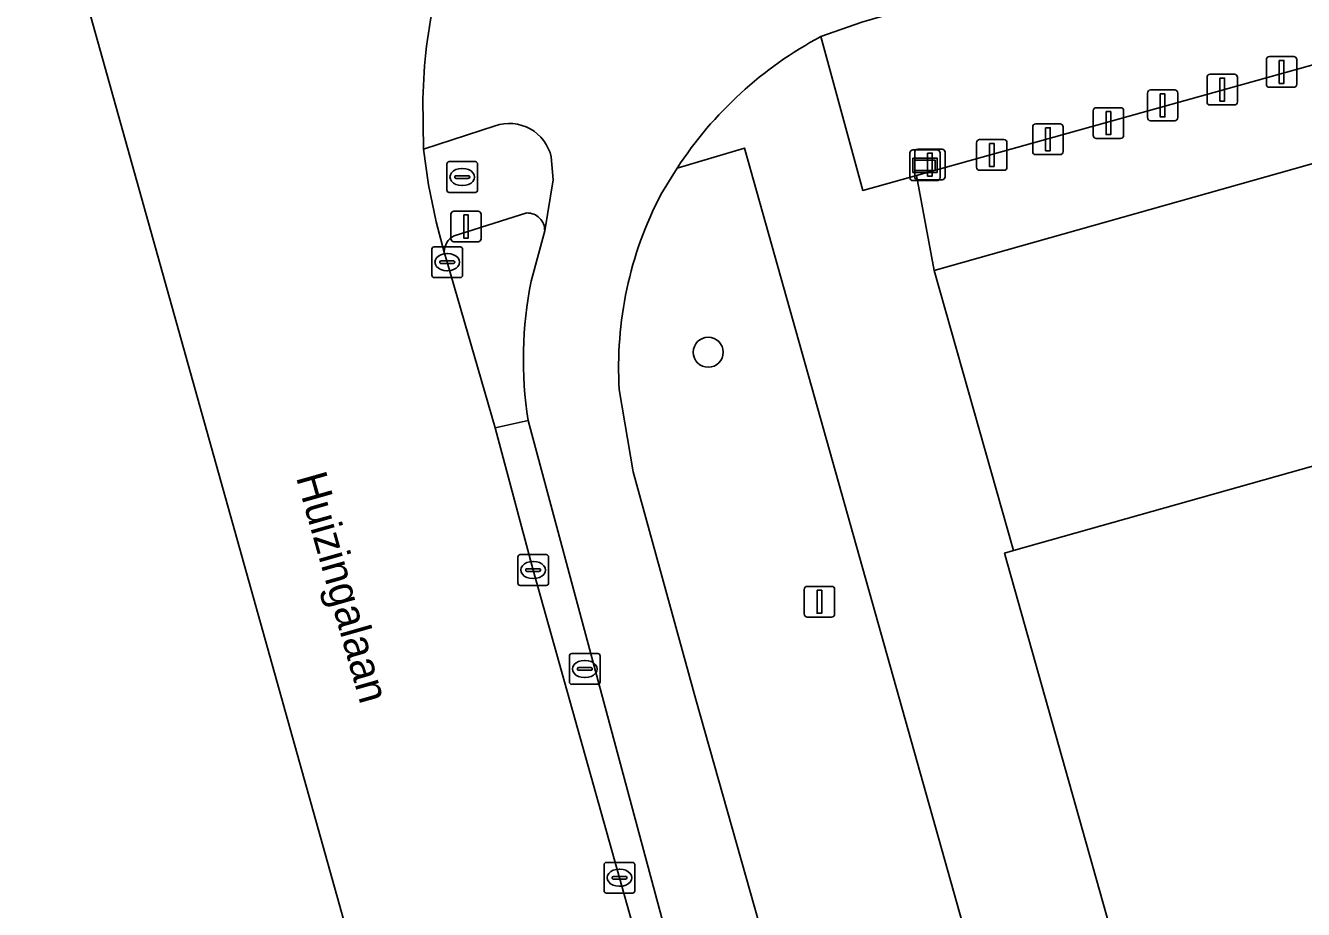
# Model space of a CAD drawing. Extents: x 159680 to 160786, y 387323 to 388340.
# Drawn here: x 159679.9 to 159721.53, y 388136.03 to 388164.81 of the extents above; entities that cross this region are included whole.
import ezdxf

# ---------------------------------------------------------------- set-up
doc = ezdxf.new("R2010")
doc.units = 0
for name, color, linetype in [('IMGEO_Afsluitpaal', 7, 'Continuous'), ('IMGEO_Berm_groen', 7, 'Continuous'), ('IMGEO_Berm_open', 7, 'Continuous'), ('IMGEO_Boom', 7, 'Continuous'), ('IMGEO_Fietspad_gesloten', 7, 'Continuous'), ('IMGEO_Groenvoorziening', 7, 'Continuous'), ('IMGEO_Kolk', 7, 'Continuous'), ('IMGEO_Lichtmast', 7, 'Continuous'), ('IMGEO_Openbare_ruimte_label', 7, 'Continuous'), ('IMGEO_Pand', 7, 'Continuous'), ('IMGEO_Parkeervlak_open', 7, 'Continuous'), ('IMGEO_Rijbaan_regionaal_gesloten', 7, 'Continuous'), ('IMGEO_Rioolput', 7, 'Continuous'), ('IMGEO_Verkeerseiland_groen', 7, 'Continuous'), ('IMGEO_Verkeersregelinstallatiepaal', 7, 'Continuous'), ('IMGEO_Verklikker', 7, 'Continuous'), ('IMGEO_Voetpad_open', 7, 'Continuous')]:
    doc.layers.add(name, color=color, linetype=linetype)

msp = doc.modelspace()

# ---------------------------------------------------------------- linework, layer by layer
at = {"layer": 'IMGEO_Afsluitpaal'}
for p, q in [((159720.32, 388162.901), (159720.32, 388163.701)), ((159720.32, 388163.701), (159720.32, 388162.901)), ((159720.42, 388163.801), (159721.21, 388163.801)), ((159721.21, 388163.801), (159720.42, 388163.801)), ((159721.31, 388163.701), (159721.31, 388162.901)), ((159721.31, 388162.901), (159721.31, 388163.701)), ((159718.485, 388163.227), (159719.275, 388163.227)), ((159719.275, 388163.227), (159718.485, 388163.227)), ((159718.385, 388162.327), (159718.385, 388163.127)), ((159718.385, 388163.127), (159718.385, 388162.327)), ((159719.375, 388163.127), (159719.375, 388162.327)), ((159719.375, 388162.327), (159719.375, 388163.127)), ((159721.21, 388162.801), (159720.42, 388162.801)), ((159720.42, 388162.801), (159721.21, 388162.801)), ((159716.444, 388161.813), (159716.444, 388162.613)), ((159716.444, 388162.613), (159716.444, 388161.813)), ((159716.544, 388162.713), (159717.334, 388162.713)), ((159717.334, 388162.713), (159716.544, 388162.713)), ((159717.434, 388162.613), (159717.434, 388161.813)), ((159717.434, 388161.813), (159717.434, 388162.613)), ((159714.677, 388161.235), (159714.677, 388162.035)), ((159714.677, 388162.035), (159714.677, 388161.235)), ((159714.777, 388162.135), (159715.567, 388162.135)), ((159715.567, 388162.135), (159714.777, 388162.135)), ((159715.667, 388162.035), (159715.667, 388161.235)), ((159715.667, 388161.235), (159715.667, 388162.035)), ((159719.275, 388162.227), (159718.485, 388162.227)), ((159718.485, 388162.227), (159719.275, 388162.227)), ((159712.806, 388161.609), (159713.596, 388161.609)), ((159713.596, 388161.609), (159712.806, 388161.609)), ((159717.334, 388161.713), (159716.544, 388161.713)), ((159716.544, 388161.713), (159717.334, 388161.713)), ((159712.706, 388160.709), (159712.706, 388161.509)), ((159712.706, 388161.509), (159712.706, 388160.709)), ((159713.696, 388161.509), (159713.696, 388160.709)), ((159713.696, 388160.709), (159713.696, 388161.509)), ((159715.567, 388161.135), (159714.777, 388161.135)), ((159714.777, 388161.135), (159715.567, 388161.135)), ((159708.964, 388160.786), (159709.754, 388160.786)), ((159709.754, 388160.786), (159708.964, 388160.786)), ((159710.877, 388160.197), (159710.877, 388160.997)), ((159710.877, 388160.997), (159710.877, 388160.197)), ((159710.977, 388161.097), (159711.767, 388161.097)), ((159711.767, 388161.097), (159710.977, 388161.097)), ((159711.867, 388160.997), (159711.867, 388160.197)), ((159711.867, 388160.197), (159711.867, 388160.997)), ((159708.864, 388159.886), (159708.864, 388160.686)), ((159708.864, 388160.686), (159708.864, 388159.886)), ((159709.854, 388160.686), (159709.854, 388159.886)), ((159709.854, 388159.886), (159709.854, 388160.686)), ((159713.596, 388160.609), (159712.806, 388160.609)), ((159712.806, 388160.609), (159713.596, 388160.609)), ((159711.767, 388160.097), (159710.977, 388160.097)), ((159710.977, 388160.097), (159711.767, 388160.097)), ((159709.754, 388159.786), (159708.964, 388159.786)), ((159708.964, 388159.786), (159709.754, 388159.786))]:
    msp.add_line(p, q, dxfattribs=at)
for points in [[(159720.74, 388163.676), (159720.89, 388163.676), (159720.89, 388162.926), (159720.74, 388162.926), (159720.74, 388163.676)], [(159718.805, 388163.102), (159718.955, 388163.102), (159718.955, 388162.352), (159718.805, 388162.352), (159718.805, 388163.102)], [(159716.864, 388162.588), (159717.014, 388162.588), (159717.014, 388161.838), (159716.864, 388161.838), (159716.864, 388162.588)], [(159715.097, 388162.01), (159715.247, 388162.01), (159715.247, 388161.26), (159715.097, 388161.26), (159715.097, 388162.01)], [(159713.126, 388161.484), (159713.276, 388161.484), (159713.276, 388160.734), (159713.126, 388160.734), (159713.126, 388161.484)], [(159711.297, 388160.972), (159711.447, 388160.972), (159711.447, 388160.222), (159711.297, 388160.222), (159711.297, 388160.972)], [(159709.284, 388160.661), (159709.434, 388160.661), (159709.434, 388159.911), (159709.284, 388159.911), (159709.284, 388160.661)]]:
    msp.add_lwpolyline(points, dxfattribs=at)
for centre, start, end in [((159720.42, 388163.701), 90, 180), ((159720.42, 388163.701), 90, 180), ((159721.21, 388163.701), 0, 90), ((159721.21, 388163.701), 360, 90), ((159718.485, 388163.127), 90, 180), ((159718.485, 388163.127), 90, 180), ((159719.275, 388163.127), 0, 90), ((159719.275, 388163.127), 360, 90), ((159720.42, 388162.901), 180, 270), ((159720.42, 388162.901), 180, 270), ((159721.21, 388162.901), 270, 0), ((159721.21, 388162.901), 270, 0), ((159716.544, 388162.613), 90, 180), ((159716.544, 388162.613), 90, 180), ((159717.334, 388162.613), 0, 90), ((159717.334, 388162.613), 360, 90), ((159714.777, 388162.035), 90, 180), ((159714.777, 388162.035), 90, 180), ((159715.567, 388162.035), 0, 90), ((159715.567, 388162.035), 360, 90), ((159718.485, 388162.327), 180, 270), ((159718.485, 388162.327), 180, 270), ((159719.275, 388162.327), 270, 0), ((159719.275, 388162.327), 270, 0), ((159712.806, 388161.509), 90, 180), ((159712.806, 388161.509), 90, 180), ((159713.596, 388161.509), 0, 90), ((159713.596, 388161.509), 360, 90), ((159716.544, 388161.813), 180, 270), ((159716.544, 388161.813), 180, 270), ((159717.334, 388161.813), 270, 0), ((159717.334, 388161.813), 270, 0), ((159714.777, 388161.235), 180, 270), ((159714.777, 388161.235), 180, 270), ((159715.567, 388161.235), 270, 0), ((159715.567, 388161.235), 270, 0), ((159708.964, 388160.686), 90, 180), ((159708.964, 388160.686), 90, 180), ((159709.754, 388160.686), 0, 90), ((159709.754, 388160.686), 360, 90), ((159710.977, 388160.997), 90, 180), ((159710.977, 388160.997), 90, 180), ((159711.767, 388160.997), 0, 90), ((159711.767, 388160.997), 360, 90), ((159712.806, 388160.709), 180, 270), ((159712.806, 388160.709), 180, 270), ((159713.596, 388160.709), 270, 0), ((159713.596, 388160.709), 270, 0), ((159708.964, 388159.886), 180, 270), ((159708.964, 388159.886), 180, 270), ((159709.754, 388159.886), 270, 0), ((159709.754, 388159.886), 270, 0), ((159710.977, 388160.197), 180, 270), ((159710.977, 388160.197), 180, 270), ((159711.767, 388160.197), 270, 0), ((159711.767, 388160.197), 270, 0)]:
    msp.add_arc(centre, 0.1, start, end, dxfattribs=at)
at = {"layer": 'IMGEO_Berm_groen'}
for points in [[(159703.321, 388160.82), (159701.126, 388160.169), (159700.596, 388159.313)], [(159719.517, 388103.237), (159703.321, 388160.82)], [(159699.238, 388152.96), (159699.688, 388150.278), (159701.735, 388142.864), (159713.692, 388100.589), (159718.952, 388102.096)]]:
    msp.add_lwpolyline(points, dxfattribs=at)
msp.add_arc((159711.369, 388153.689), 12.152, 152.431, 183.4374, dxfattribs=at)
at = {"layer": 'IMGEO_Berm_open'}
msp.add_lwpolyline([(159708.235, 388108.71), (159701.005, 388134.325), (159696.271, 388151.945), (159695.201, 388151.706), (159696.434, 388147.08), (159699.246, 388137.059), (159702.063, 388127.028), (159704.613, 388117.962), (159707.423, 388107.93), (159709.976, 388098.854), (159712.776, 388088.821), (159713.105, 388087.616)], dxfattribs=at)
at = {"layer": 'IMGEO_Boom'}
msp.add_circle((159702.136, 388154.171), 0.489, dxfattribs=at)
at = {"layer": 'IMGEO_Fietspad_gesloten'}
for points in [[(159705.804, 388164.452), (159707.145, 388164.927), (159721.106, 388168.977), (159723.633, 388169.719), (159723.456, 388169.745)], [(159692.843, 388162.429), (159692.861, 388160.79), (159695.195, 388161.544)], [(159697.023, 388160.532), (159697.09, 388159.791), (159696.81, 388158.125), (159696.37, 388156.492)], [(159700.596, 388159.313), (159701.126, 388160.169)], [(159717.808, 388086.632), (159716.977, 388089.069), (159716.203, 388091.736), (159715.317, 388094.804), (159714.543, 388097.489), (159713.692, 388100.589), (159701.735, 388142.864), (159699.688, 388150.278), (159699.238, 388152.96)], [(159696.271, 388151.945), (159701.005, 388134.325), (159708.235, 388108.71), (159713.8, 388089.138), (159714.922, 388085.647)]]:
    msp.add_lwpolyline(points, dxfattribs=at)
for centre, radius, start, end in [((159708.554, 388162.193), 15.712, 166.5996, 179.1379), ((159711.797, 388153.21), 12.74, 118.0621, 146.89), ((159695.658, 388160.223), 1.399, 12.7415, 109.3197), ((159711.369, 388153.689), 12.152, 152.431, 183.4374), ((159708.931, 388153.944), 12.817, 168.5329, 188.9726)]:
    msp.add_arc(centre, radius, start, end, dxfattribs=at)
at = {"layer": 'IMGEO_Groenvoorziening'}
msp.add_lwpolyline([(159724.653, 388169.975), (159723.633, 388169.719), (159721.106, 388168.977), (159707.145, 388164.927), (159705.804, 388164.452), (159707.169, 388159.441), (159708.924, 388159.928), (159749.997, 388171.408)], dxfattribs=at)
at = {"layer": 'IMGEO_Kolk'}
for p, q in [((159693.135, 388156.679), (159693.135, 388157.531)), ((159693.21, 388157.605), (159694.062, 388157.605)), ((159693.623, 388157.385), (159693.648, 388157.385)), ((159694.136, 388157.531), (159694.136, 388156.679)), ((159693.394, 388157.099), (159693.394, 388157.111)), ((159693.832, 388157.062), (159693.434, 388157.062)), ((159693.437, 388157.148), (159693.835, 388157.148)), ((159693.878, 388157.111), (159693.878, 388157.099)), ((159694.062, 388156.605), (159693.21, 388156.605)), ((159693.646, 388156.825), (159693.621, 388156.825)), ((159695.933, 388146.654), (159695.933, 388147.506)), ((159696.008, 388147.58), (159696.86, 388147.58)), ((159696.934, 388147.506), (159696.934, 388146.654)), ((159696.192, 388147.074), (159696.192, 388147.086)), ((159696.63, 388147.037), (159696.232, 388147.037)), ((159696.235, 388147.123), (159696.633, 388147.123)), ((159696.421, 388147.36), (159696.446, 388147.36)), ((159696.676, 388147.086), (159696.676, 388147.074)), ((159696.86, 388146.58), (159696.008, 388146.58)), ((159696.444, 388146.8), (159696.419, 388146.8)), ((159697.615, 388143.431), (159697.615, 388144.283)), ((159697.69, 388144.357), (159698.542, 388144.357)), ((159698.103, 388144.137), (159698.128, 388144.137)), ((159698.616, 388144.283), (159698.616, 388143.431)), ((159697.874, 388143.851), (159697.874, 388143.863)), ((159698.312, 388143.814), (159697.914, 388143.814)), ((159697.917, 388143.9), (159698.315, 388143.9)), ((159698.358, 388143.863), (159698.358, 388143.851)), ((159698.542, 388143.357), (159697.69, 388143.357)), ((159698.126, 388143.577), (159698.101, 388143.577)), ((159698.745, 388136.633), (159698.745, 388137.485)), ((159698.82, 388137.559), (159699.672, 388137.559)), ((159699.746, 388137.485), (159699.746, 388136.633)), ((159699.004, 388137.053), (159699.004, 388137.065)), ((159699.442, 388137.016), (159699.044, 388137.016)), ((159699.047, 388137.102), (159699.445, 388137.102)), ((159699.233, 388137.339), (159699.258, 388137.339)), ((159699.488, 388137.065), (159699.488, 388137.053)), ((159699.672, 388136.559), (159698.82, 388136.559)), ((159699.256, 388136.779), (159699.231, 388136.779))]:
    msp.add_line(p, q, dxfattribs=at)
for points in [[(159693.135, 388156.679), (159693.135, 388157.531)], [(159693.21, 388157.605), (159694.062, 388157.605)], [(159694.136, 388157.531), (159694.136, 388156.679)], [(159694.062, 388156.605), (159693.21, 388156.605)], [(159695.933, 388146.654), (159695.933, 388147.506)], [(159696.008, 388147.58), (159696.86, 388147.58)], [(159696.934, 388147.506), (159696.934, 388146.654)], [(159696.86, 388146.58), (159696.008, 388146.58)], [(159697.615, 388143.431), (159697.615, 388144.283)], [(159697.69, 388144.357), (159698.542, 388144.357)], [(159698.616, 388144.283), (159698.616, 388143.431)], [(159698.542, 388143.357), (159697.69, 388143.357)], [(159698.745, 388136.633), (159698.745, 388137.485)], [(159698.82, 388137.559), (159699.672, 388137.559)], [(159699.746, 388137.485), (159699.746, 388136.633)], [(159699.672, 388136.559), (159698.82, 388136.559)]]:
    msp.add_lwpolyline(points, dxfattribs=at)
for centre, radius, start, end in [((159693.212, 388157.529), 0.0765, 91.552, 178.448), ((159693.212, 388157.529), 0.0765, 91.552, 178.448), ((159694.06, 388157.529), 0.0765, 1.552, 88.448), ((159694.06, 388157.529), 0.0765, 1.552, 88.448), ((159693.434, 388157.108), 0.0403, 85.8775, 175.7526), ((159693.431, 388157.098), 0.0366, 178.938, 274.7102), ((159693.835, 388157.105), 0.043, 264.8664, 352.4533), ((159693.839, 388157.11), 0.0386, 1.7309, 96.639), ((159693.212, 388156.681), 0.0765, 181.552, 268.448), ((159693.212, 388156.681), 0.0765, 181.552, 268.448), ((159694.06, 388156.681), 0.0765, 271.552, 358.448), ((159694.06, 388156.681), 0.0765, 271.552, 358.448), ((159696.01, 388147.504), 0.0765, 91.552, 178.448), ((159696.01, 388147.504), 0.0765, 91.552, 178.448), ((159696.858, 388147.504), 0.0765, 1.552, 88.448), ((159696.858, 388147.504), 0.0765, 1.552, 88.448), ((159696.232, 388147.083), 0.0403, 85.8775, 175.7526), ((159696.229, 388147.073), 0.0366, 178.938, 274.7102), ((159696.633, 388147.08), 0.043, 264.8664, 352.4533), ((159696.637, 388147.085), 0.0386, 1.7309, 96.639), ((159696.01, 388146.656), 0.0765, 181.552, 268.448), ((159696.01, 388146.656), 0.0765, 181.552, 268.448), ((159696.858, 388146.656), 0.0765, 271.552, 358.448), ((159696.858, 388146.656), 0.0765, 271.552, 358.448), ((159697.692, 388144.281), 0.0765, 91.552, 178.448), ((159697.692, 388144.281), 0.0765, 91.552, 178.448), ((159698.54, 388144.281), 0.0765, 1.552, 88.448), ((159698.54, 388144.281), 0.0765, 1.552, 88.448), ((159697.914, 388143.86), 0.0403, 85.8775, 175.7526), ((159697.911, 388143.85), 0.0366, 178.938, 274.7102), ((159698.315, 388143.857), 0.043, 264.8664, 352.4533), ((159698.319, 388143.862), 0.0386, 1.7309, 96.639), ((159697.692, 388143.433), 0.0765, 181.552, 268.448), ((159697.692, 388143.433), 0.0765, 181.552, 268.448), ((159698.54, 388143.433), 0.0765, 271.552, 358.448), ((159698.54, 388143.433), 0.0765, 271.552, 358.448), ((159698.822, 388137.483), 0.0765, 91.552, 178.448), ((159698.822, 388137.483), 0.0765, 91.552, 178.448), ((159699.67, 388137.483), 0.0765, 1.552, 88.448), ((159699.67, 388137.483), 0.0765, 1.552, 88.448), ((159699.044, 388137.062), 0.0403, 85.8775, 175.7526), ((159699.041, 388137.052), 0.0366, 178.938, 274.7102), ((159699.445, 388137.059), 0.043, 264.8664, 352.4533), ((159699.449, 388137.064), 0.0386, 1.7309, 96.639), ((159698.822, 388136.635), 0.0765, 181.552, 268.448), ((159698.822, 388136.635), 0.0765, 181.552, 268.448), ((159699.67, 388136.635), 0.0765, 271.552, 358.448), ((159699.67, 388136.635), 0.0765, 271.552, 358.448)]:
    msp.add_arc(centre, radius, start, end, dxfattribs=at)
for centre, major_axis, ratio, start_param, end_param in [((159693.622, 388157.105), (-0.387, 0.002), 0.722429, 4.712389, 7.853982), ((159693.647, 388157.105), (-0.39, 0.002), 0.717154, 1.570796, 4.712389), ((159696.42, 388147.08), (-0.387, 0.002), 0.722429, 4.712389, 7.853982), ((159696.445, 388147.08), (-0.39, 0.002), 0.717154, 1.570796, 4.712389), ((159698.102, 388143.857), (-0.387, 0.002), 0.722429, 4.712389, 7.853982), ((159698.127, 388143.857), (-0.39, 0.002), 0.717154, 1.570796, 4.712389), ((159699.232, 388137.059), (-0.387, 0.002), 0.722429, 4.712389, 7.853982), ((159699.257, 388137.059), (-0.39, 0.002), 0.717154, 1.570796, 4.712389)]:
    msp.add_ellipse(centre, major_axis=major_axis, ratio=ratio, start_param=start_param, end_param=end_param, dxfattribs=at)
at = {"layer": 'IMGEO_Lichtmast'}
for p, q in [((159705.263, 388145.648), (159705.263, 388146.448)), ((159705.263, 388146.448), (159705.263, 388145.648)), ((159705.363, 388146.548), (159706.153, 388146.548)), ((159706.153, 388146.548), (159705.363, 388146.548)), ((159706.253, 388146.448), (159706.253, 388145.648)), ((159706.253, 388145.648), (159706.253, 388146.448)), ((159706.153, 388145.548), (159705.363, 388145.548)), ((159705.363, 388145.548), (159706.153, 388145.548))]:
    msp.add_line(p, q, dxfattribs=at)
msp.add_lwpolyline([(159705.683, 388146.423), (159705.833, 388146.423), (159705.833, 388145.673), (159705.683, 388145.673), (159705.683, 388146.423)], dxfattribs=at)
for centre, start, end in [((159705.363, 388146.448), 90, 180), ((159705.363, 388146.448), 90, 180), ((159706.153, 388146.448), 0, 90), ((159706.153, 388146.448), 360, 90), ((159705.363, 388145.648), 180, 270), ((159705.363, 388145.648), 180, 270), ((159706.153, 388145.648), 270, 0), ((159706.153, 388145.648), 270, 0)]:
    msp.add_arc(centre, 0.1, start, end, dxfattribs=at)
at = {"layer": 'IMGEO_Pand'}
msp.add_lwpolyline([(159730.739, 388081.596), (159758.926, 388089.554), (159763.767, 388090.921), (159762.15, 388096.648), (159757.31, 388095.283), (159752.877, 388110.972), (159752.702, 388110.923), (159751.863, 388113.893), (159775.062, 388120.447), (159768.044, 388145.288), (159763.459, 388161.519), (159763.357, 388161.491), (159739.302, 388154.694), (159739.248, 388154.887), (159739.21, 388155.023), (159735.05, 388153.839), (159734.959, 388154.16), (159712.08, 388147.715), (159711.789, 388147.633), (159723.951, 388104.478), (159724.304, 388103.226), (159724.606, 388103.311), (159727.841, 388091.857), (159728.897, 388088.118)], dxfattribs=at)
at = {"layer": 'IMGEO_Parkeervlak_open'}
msp.add_lwpolyline([(159750.791, 388168.5), (159709.502, 388156.836), (159712.08, 388147.715), (159734.959, 388154.16)], dxfattribs=at)
at = {"layer": 'IMGEO_Rijbaan_regionaal_gesloten'}
for points in [[(159696.673, 388170.966), (159695.066, 388176.939), (159679.898, 388172.707), (159702.382, 388092.39)], [(159713.105, 388087.616), (159712.776, 388088.821), (159709.976, 388098.854), (159707.423, 388107.93), (159704.613, 388117.962), (159702.063, 388127.028), (159699.246, 388137.059), (159696.434, 388147.08), (159695.201, 388151.706), (159693.636, 388157.105), (159693.538, 388157.435), (159693.27, 388158.421), (159693.025, 388159.619), (159692.861, 388160.79), (159692.843, 388162.429)]]:
    msp.add_lwpolyline(points, dxfattribs=at)
msp.add_arc((159708.554, 388162.193), 15.712, 166.5996, 179.1379, dxfattribs=at)
at = {"layer": 'IMGEO_Rioolput'}
for p, q in [((159693.623, 388159.453), (159693.623, 388160.305)), ((159693.698, 388160.379), (159694.55, 388160.379)), ((159694.624, 388160.305), (159694.624, 388159.453)), ((159693.882, 388159.873), (159693.882, 388159.885)), ((159693.925, 388159.922), (159694.323, 388159.922)), ((159694.111, 388160.159), (159694.136, 388160.159)), ((159694.366, 388159.885), (159694.366, 388159.873)), ((159694.32, 388159.836), (159693.922, 388159.836)), ((159694.134, 388159.599), (159694.109, 388159.599)), ((159694.55, 388159.379), (159693.698, 388159.379))]:
    msp.add_line(p, q, dxfattribs=at)
for points in [[(159693.623, 388159.453), (159693.623, 388160.305)], [(159693.698, 388160.379), (159694.55, 388160.379)], [(159694.624, 388160.305), (159694.624, 388159.453)], [(159694.55, 388159.379), (159693.698, 388159.379)]]:
    msp.add_lwpolyline(points, dxfattribs=at)
for centre, radius, start, end in [((159693.7, 388160.303), 0.0765, 91.552, 178.448), ((159693.7, 388160.303), 0.0765, 91.552, 178.448), ((159694.548, 388160.303), 0.0765, 1.552, 88.448), ((159694.548, 388160.303), 0.0765, 1.552, 88.448), ((159693.922, 388159.882), 0.0403, 85.8775, 175.7526), ((159693.919, 388159.872), 0.0366, 178.938, 274.7102), ((159694.323, 388159.879), 0.043, 264.8664, 352.4533), ((159694.327, 388159.884), 0.0386, 1.7309, 96.639), ((159693.7, 388159.455), 0.0765, 181.552, 268.448), ((159693.7, 388159.455), 0.0765, 181.552, 268.448), ((159694.548, 388159.455), 0.0765, 271.552, 358.448), ((159694.548, 388159.455), 0.0765, 271.552, 358.448)]:
    msp.add_arc(centre, radius, start, end, dxfattribs=at)
for centre, major_axis, ratio, start_param, end_param in [((159694.11, 388159.879), (-0.387, 0.002), 0.722429, 4.712389, 7.853982), ((159694.135, 388159.879), (-0.39, 0.002), 0.717154, 1.570796, 4.712389)]:
    msp.add_ellipse(centre, major_axis=major_axis, ratio=ratio, start_param=start_param, end_param=end_param, dxfattribs=at)
at = {"layer": 'IMGEO_Verkeerseiland_groen'}
for points in [[(159696.229, 388158.708), (159693.856, 388157.959)], [(159696.37, 388156.492), (159696.81, 388158.125)], [(159693.538, 388157.435), (159693.636, 388157.105), (159695.201, 388151.706), (159696.271, 388151.945)]]:
    msp.add_lwpolyline(points, dxfattribs=at)
for centre, radius, start, end in [((159696.238, 388158.136), 0.572, 358.8527, 90.9504), ((159694.111, 388157.446), 0.573, 116.428, 181.0674), ((159708.931, 388153.944), 12.817, 168.5329, 188.9726)]:
    msp.add_arc(centre, radius, start, end, dxfattribs=at)
at = {"layer": 'IMGEO_Verkeersregelinstallatiepaal'}
for p, q in [((159693.751, 388157.867), (159693.751, 388158.667)), ((159693.751, 388158.667), (159693.751, 388157.867)), ((159693.851, 388158.767), (159694.641, 388158.767)), ((159694.641, 388158.767), (159693.851, 388158.767)), ((159694.741, 388158.667), (159694.741, 388157.867)), ((159694.741, 388157.867), (159694.741, 388158.667)), ((159694.641, 388157.767), (159693.851, 388157.767)), ((159693.851, 388157.767), (159694.641, 388157.767))]:
    msp.add_line(p, q, dxfattribs=at)
msp.add_lwpolyline([(159694.171, 388158.642), (159694.321, 388158.642), (159694.321, 388157.892), (159694.171, 388157.892), (159694.171, 388158.642)], dxfattribs=at)
for centre, start, end in [((159693.851, 388158.667), 90, 180), ((159693.851, 388158.667), 90, 180), ((159694.641, 388158.667), 0, 90), ((159694.641, 388158.667), 360, 90), ((159693.851, 388157.867), 180, 270), ((159693.851, 388157.867), 180, 270), ((159694.641, 388157.867), 270, 0), ((159694.641, 388157.867), 270, 0)]:
    msp.add_arc(centre, 0.1, start, end, dxfattribs=at)
at = {"layer": 'IMGEO_Verklikker'}
for p, q in [((159708.803, 388160.762), (159709.593, 388160.762)), ((159709.593, 388160.762), (159708.803, 388160.762)), ((159708.703, 388159.862), (159708.703, 388160.662)), ((159708.703, 388160.662), (159708.703, 388159.862)), ((159709.693, 388160.662), (159709.693, 388159.862)), ((159709.693, 388159.862), (159709.693, 388160.662)), ((159709.593, 388159.762), (159708.803, 388159.762)), ((159708.803, 388159.762), (159709.593, 388159.762))]:
    msp.add_line(p, q, dxfattribs=at)
for points in [[(159708.804, 388160.494), (159709.592, 388160.494), (159709.592, 388160.03), (159708.804, 388160.03), (159708.804, 388160.494)], [(159708.869, 388160.429), (159708.869, 388160.095), (159709.527, 388160.095), (159709.527, 388160.429), (159708.869, 388160.429)]]:
    msp.add_lwpolyline(points, dxfattribs=at)
for centre, start, end in [((159708.803, 388160.662), 90, 180), ((159708.803, 388160.662), 90, 180), ((159709.593, 388160.662), 0, 90), ((159709.593, 388160.662), 360, 90), ((159708.803, 388159.862), 180, 270), ((159708.803, 388159.862), 180, 270), ((159709.593, 388159.862), 270, 0), ((159709.593, 388159.862), 270, 0)]:
    msp.add_arc(centre, 0.1, start, end, dxfattribs=at)
at = {"layer": 'IMGEO_Voetpad_open'}
msp.add_lwpolyline([(159750.791, 388168.5), (159749.997, 388171.408), (159708.924, 388159.928), (159709.502, 388156.836)], close=True, dxfattribs=at)
for points in [[(159711.789, 388147.633), (159712.08, 388147.715), (159709.502, 388156.836), (159708.924, 388159.928), (159707.169, 388159.441), (159705.804, 388164.452)], [(159695.195, 388161.544), (159692.861, 388160.79)], [(159692.861, 388160.79), (159693.025, 388159.619), (159693.27, 388158.421), (159693.538, 388157.435)], [(159701.126, 388160.169), (159703.321, 388160.82), (159719.517, 388103.237), (159722.959, 388104.2), (159723.951, 388104.478), (159711.789, 388147.633)], [(159696.81, 388158.125), (159697.09, 388159.791), (159697.023, 388160.532)], [(159693.856, 388157.959), (159696.229, 388158.708)]]:
    msp.add_lwpolyline(points, dxfattribs=at)
for centre, radius, start, end in [((159711.797, 388153.21), 12.74, 118.0621, 146.89), ((159695.658, 388160.223), 1.399, 12.7415, 109.3197), ((159696.238, 388158.136), 0.572, 358.8527, 90.9504), ((159694.111, 388157.446), 0.573, 116.428, 181.0674)]:
    msp.add_arc(centre, radius, start, end, dxfattribs=at)

# ---------------------------------------------------------------- texts
at = {"layer": 'IMGEO_Openbare_ruimte_label'}
msp.add_text('Huizingalaan', height=1, rotation=285.8431, dxfattribs=at).set_placement((159688.703, 388150.107))

doc.saveas('drawing.dxf')
